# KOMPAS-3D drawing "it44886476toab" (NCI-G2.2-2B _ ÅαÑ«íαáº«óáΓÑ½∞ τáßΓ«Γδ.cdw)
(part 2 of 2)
  Кривая без истории:10764
  Кривая без истории:10765
  Кривая без истории:10766
  Кривая без истории:10767
  Кривая без истории:10768
  Кривая без истории:10769
  Кривая без истории:10770
  Кривая без истории:10771
  Кривая без истории:10772
  Кривая без истории:10773
  Кривая без истории:10774
  Кривая без истории:10775
  Кривая без истории:10776
  Кривая без истории:10777
  Кривая без истории:10778
  Кривая без истории:10779
  Кривая без истории:10780
  Кривая без истории:10781
  Кривая без истории:10782
  Кривая без истории:10783
  Кривая без истории:10784
  Кривая без истории:10785
  Кривая без истории:10786
  Кривая без истории:10787
  Кривая без истории:10788
  Кривая без истории:10789
  Кривая без истории:10790
  Кривая без истории:10791
  Кривая без истории:10792
  Кривая без истории:10793
  Кривая без истории:10794
  Кривая без истории:10795
  Кривая без истории:10796
  Кривая без истории:10797
  Кривая без истории:10798
  Кривая без истории:10799
  Кривая без истории:10800
  Кривая без истории:10801
  Кривая без истории:10802
  Кривая без истории:10803
  Кривая без истории:10804
  Кривая без истории:10805
  Кривая без истории:10806
  Кривая без истории:10807
  Кривая без истории:10808
  Кривая без истории:10809
  Кривая без истории:10810
  Кривая без истории:10811
  Кривая без истории:10812
  Кривая без истории:10813
  Кривая без истории:10814
  Кривая без истории:10815
  Кривая без истории:10816
  Кривая без истории:10817
  Кривая без истории:10818
  Кривая без истории:10819
  Кривая без истории:10820
  Кривая без истории:10821
  Кривая без истории:10822
  Кривая без истории:10823
  Кривая без истории:10824
  Кривая без истории:10825
  Кривая без истории:10826
  Кривая без истории:10827
  Кривая без истории:10828
  Кривая без истории:10829
  Кривая без истории:10830
  Кривая без истории:10831
  Кривая без истории:10832
  Кривая без истории:10833
  Кривая без истории:10834
  Кривая без истории:10835
  Кривая без истории:10836
  Кривая без истории:10837
  Кривая без истории:10838
  Кривая без истории:10839
  Кривая без истории:10840
  Кривая без истории:10841
  Кривая без истории:10842
  Кривая без истории:10843
  Кривая без истории:10844
  Кривая без истории:10845
  Кривая без истории:10846
  Кривая без истории:10847
  Кривая без истории:10848
  Кривая без истории:10849
  Кривая без истории:10850
  Кривая без истории:10851
  Кривая без истории:10852
  Кривая без истории:10853
  Кривая без истории:10854
  Кривая без истории:10855
  Кривая без истории:10856
  Кривая без истории:10857
  Кривая без истории:10858
  Кривая без истории:10859
  Кривая без истории:10860
  Кривая без истории:10861
  Кривая без истории:10862
  Кривая без истории:10863
  Кривая без истории:10864
  Кривая без истории:10865
  Кривая без истории:10866
  Кривая без истории:10867
  Кривая без истории:10868
  Кривая без истории:10869
  Кривая без истории:10870
  Кривая без истории:10871
  Кривая без истории:10872
  Кривая без истории:10873
  Кривая без истории:10874
  Кривая без истории:10875
  Кривая без истории:10876
  Кривая без истории:10877
  Кривая без истории:10878
  Кривая без истории:10879
  Кривая без истории:10880
  Кривая без истории:10881
  Кривая без истории:10882
  Кривая без истории:10883
  Кривая без истории:10884
  Кривая без истории:10885
  Кривая без истории:10886
  Кривая без истории:10887
  Кривая без истории:10888
  Кривая без истории:10889
  Кривая без истории:10890
  Кривая без истории:10891
  Кривая без истории:10892
  Кривая без истории:10893
  Кривая без истории:10894
  Кривая без истории:10895
  Кривая без истории:10896
  Кривая без истории:10897
  Кривая без истории:10898
  Кривая без истории:10899
  Кривая без истории:10900
  Кривая без истории:10901
  Кривая без истории:10902
  Кривая без истории:10903
  Кривая без истории:10904
  Кривая без истории:10905
  Кривая без истории:10906
  Кривая без истории:10907
  Кривая без истории:10908
  Кривая без истории:10909
  Кривая без истории:10910
  Кривая без истории:10911
  Кривая без истории:10912
  Кривая без истории:10913
  Кривая без истории:10914
  Кривая без истории:10915
  Кривая без истории:10916
  Кривая без истории:10917
  Кривая без истории:10918
  Кривая без истории:10919
  Кривая без истории:10920
  Кривая без истории:10921
  Кривая без истории:10922
  Кривая без истории:10923
  Кривая без истории:10924
  Кривая без истории:10925
  Кривая без истории:10926
  Кривая без истории:10927
  Кривая без истории:10928
  Кривая без истории:10929
  Кривая без истории:10930
  Кривая без истории:10931
  Кривая без истории:10932
  Кривая без истории:10933
  Кривая без истории:10934
  Кривая без истории:10935
  Кривая без истории:10936
  Кривая без истории:10937
  Кривая без истории:10938
  Кривая без истории:10939
  Кривая без истории:10940
  Кривая без истории:10941
  Кривая без истории:10942
  Кривая без истории:10943
  Кривая без истории:10944
  Кривая без истории:10945
  Кривая без истории:10946
  Кривая без истории:10947
  Кривая без истории:10948
  Кривая без истории:10949
  Кривая без истории:10950
  Кривая без истории:10951
  Кривая без истории:10952
  Кривая без истории:10953
  Кривая без истории:10954
  Кривая без истории:10955
  Кривая без истории:10956
  Кривая без истории:10957
  Кривая без истории:10958
  Кривая без истории:10959
  Кривая без истории:10960
  Кривая без истории:10961
  Кривая без истории:10962
  Кривая без истории:10963
  Кривая без истории:10964
  Кривая без истории:10965
  Кривая без истории:10966
  Кривая без истории:10967
  Кривая без истории:10968
  Кривая без истории:10969
  Кривая без истории:10970
  Кривая без истории:10971
  Кривая без истории:10972
  Кривая без истории:10973
  Кривая без истории:10974
  Кривая без истории:10975
  Кривая без истории:10976
  Кривая без истории:10977
  Кривая без истории:10978
  Кривая без истории:10979
  Кривая без истории:10980
  Кривая без истории:10981
  Кривая без истории:10982
  Кривая без истории:10983
  Кривая без истории:10984
  Кривая без истории:10985
  Кривая без истории:10986
  Кривая без истории:10987
  Кривая без истории:10988
  Кривая без истории:10989
  Кривая без истории:10990
  Кривая без истории:10991
  Кривая без истории:10992
  Кривая без истории:10993
  Кривая без истории:10994
  Кривая без истории:10995
  Кривая без истории:10996
  Кривая без истории:10997
  Кривая без истории:10998
  Кривая без истории:10999
  Кривая без истории:11000
  Кривая без истории:11001
  Кривая без истории:11002
  Кривая без истории:11003
  Кривая без истории:11004
  Кривая без истории:11005
  Кривая без истории:11006
  Кривая без истории:11007
  Кривая без истории:11008
  Кривая без истории:11009
  Кривая без истории:11010
  Кривая без истории:11011
  Кривая без истории:11012
  Кривая без истории:11013
  Кривая без истории:11014
  Кривая без истории:11015
  Кривая без истории:11016
  Кривая без истории:11017
  Кривая без истории:11018
  Кривая без истории:11019
  Кривая без истории:11020
  Кривая без истории:11021
  Кривая без истории:11022
  Кривая без истории:11023
  Кривая без истории:11024
  Кривая без истории:11025
  Кривая без истории:11026
  Кривая без истории:11027
  Кривая без истории:11028
  Кривая без истории:11029
  Кривая без истории:11030
  Кривая без истории:11031
  Кривая без истории:11032
  Кривая без истории:11033
  Кривая без истории:11034
  Кривая без истории:11035
  Кривая без истории:11036
  Кривая без истории:11037
  Кривая без истории:11038
  Кривая без истории:11039
  Кривая без истории:11040
  Кривая без истории:11041
  Кривая без истории:11042
  Кривая без истории:11043
  Кривая без истории:11044
  Кривая без истории:11045
  Кривая без истории:11046
  Кривая без истории:11047
  Кривая без истории:11048
  Кривая без истории:11049
  Кривая без истории:11050
  Кривая без истории:11051
  Кривая без истории:11052
  Кривая без истории:11053
  Кривая без истории:11054
  Кривая без истории:11055
  Кривая без истории:11056
  Кривая без истории:11057
  Кривая без истории:11058
  Кривая без истории:11059
  Кривая без истории:11060
  Кривая без истории:11061
  Кривая без истории:11062
  Кривая без истории:11063
  Кривая без истории:11064
  Кривая без истории:11065
  Кривая без истории:11066
  Кривая без истории:11067
  Кривая без истории:11068
  Кривая без истории:11069
  Кривая без истории:11070
  Кривая без истории:11071
  Кривая без истории:11072
  Кривая без истории:11073
  Кривая без истории:11074
  Кривая без истории:11075
  Кривая без истории:11076
  Кривая без истории:11077
  Кривая без истории:11078
  Кривая без истории:11079
  Кривая без истории:11080
  Кривая без истории:11081
  Кривая без истории:11082
  Кривая без истории:11083
  Кривая без истории:11084
  Кривая без истории:11085
  Кривая без истории:11086
  Кривая без истории:11087
  Кривая без истории:11088
  Кривая без истории:11089
  Кривая без истории:11090
  Кривая без истории:11091
  Кривая без истории:11092
  Кривая без истории:11093
  Кривая без истории:11094
  Кривая без истории:11095
  Кривая без истории:11096
  Кривая без истории:11097
  Кривая без истории:11098
  Кривая без истории:11099
  Кривая без истории:11100
  Кривая без истории:11101
  Кривая без истории:11102
  Кривая без истории:11103
  Кривая без истории:11104
  Кривая без истории:11105
  Кривая без истории:11106
  Кривая без истории:11107
  Кривая без истории:11108
  Кривая без истории:11109
  Кривая без истории:11110
  Кривая без истории:11111
  Кривая без истории:11112
  Кривая без истории:11113
  Кривая без истории:11114
  Кривая без истории:11115
  Кривая без истории:11116
  Кривая без истории:11117
  Кривая без истории:11118
  Кривая без истории:11119
  Кривая без истории:11120
  Кривая без истории:11121
  Кривая без истории:11122
  Кривая без истории:11123
  Кривая без истории:11124
  Кривая без истории:11125
  Кривая без истории:11126
  Кривая без истории:11127
  Кривая без истории:11128
  Кривая без истории:11129
  Кривая без истории:11130
  Кривая без истории:11131
  Кривая без истории:11132
  Кривая без истории:11133
  Кривая без истории:11134
  Кривая без истории:11135
  Кривая без истории:11136
  Кривая без истории:11137
  Кривая без истории:11138
  Кривая без истории:11139
  Кривая без истории:11140
  Кривая без истории:11141
  Кривая без истории:11142
  Кривая без истории:11143
  Кривая без истории:11144
  Кривая без истории:11145
  Кривая без истории:11146
  Кривая без истории:11147
  Кривая без истории:11148
  Кривая без истории:11149
  Кривая без истории:11150
  Кривая без истории:11151
  Кривая без истории:11152
  Кривая без истории:11153
  Кривая без истории:11154
  Кривая без истории:11155
  Кривая без истории:11156
  Кривая без истории:11157
  Кривая без истории:11158
  Кривая без истории:11159
  Кривая без истории:11160
  Кривая без истории:11161
  Кривая без истории:11162
  Кривая без истории:11163
  Кривая без истории:11164
  Кривая без истории:11165
  Кривая без истории:11166
  Кривая без истории:11167
  Кривая без истории:11168
  Кривая без истории:11169
  Кривая без истории:11170
  Кривая без истории:11171
  Кривая без истории:11172
  Кривая без истории:11173
  Кривая без истории:11174
  Кривая без истории:11175
  Кривая без истории:11176
  Кривая без истории:11177
  Кривая без истории:11178
  Кривая без истории:11179
  Кривая без истории:11180
  Кривая без истории:11181
  Кривая без истории:11182
  Кривая без истории:11183
  Кривая без истории:11184
  Кривая без истории:11185
  Кривая без истории:11186
  Кривая без истории:11187
  Кривая без истории:11188
  Кривая без истории:11189
  Кривая без истории:11190
  Кривая без истории:11191
  Кривая без истории:11192
  Кривая без истории:11193
  Кривая без истории:11194
  Кривая без истории:11195
  Кривая без истории:11196
  Кривая без истории:11197
  Кривая без истории:11198
  Кривая без истории:11199
  Кривая без истории:11200
  Кривая без истории:11201
  Кривая без истории:11202
  Кривая без истории:11203
  Кривая без истории:11204
  Кривая без истории:11205
  Кривая без истории:11206
  Кривая без истории:11207
  Кривая без истории:11208
  Кривая без истории:11209
  Кривая без истории:11210
  Кривая без истории:11211
  Кривая без истории:11212
  Кривая без истории:11213
  Кривая без истории:11214
  Кривая без истории:11215
  Кривая без истории:11216
  Кривая без истории:11217
  Кривая без истории:11218
  Кривая без истории:11219
  Кривая без истории:11220
  Кривая без истории:11221
  Кривая без истории:11222
  Кривая без истории:11223
  Кривая без истории:11224
  Кривая без истории:11225
  Кривая без истории:11226
  Кривая без истории:11227
  Кривая без истории:11228
  Кривая без истории:11229
  Кривая без истории:11230
  Кривая без истории:11231
  Кривая без истории:11232
  Кривая без истории:11233
  Кривая без истории:11234
  Кривая без истории:11235
  Кривая без истории:11236
  Кривая без истории:11237
  Кривая без истории:11238
  Кривая без истории:11239
  Кривая без истории:11240
  Кривая без истории:11241
  Кривая без истории:11242
  Кривая без истории:11243
  Кривая без истории:11244
  Кривая без истории:11245
  Кривая без истории:11246
  Кривая без истории:11247
  Кривая без истории:11248
  Кривая без истории:11249
  Кривая без истории:11250
  Кривая без истории:11251
  Кривая без истории:11252
  Кривая без истории:11253
  Кривая без истории:11254
  Кривая без истории:11255
  Кривая без истории:11256
  Кривая без истории:11257
  Кривая без истории:11258
  Кривая без истории:11259
  Кривая без истории:11260
  Кривая без истории:11261
  Кривая без истории:11262
  Кривая без истории:11263
  Кривая без истории:11264
  Кривая без истории:11265
  Кривая без истории:11266
  Кривая без истории:11267
  Кривая без истории:11268
  Кривая без истории:11269
  Кривая без истории:11270
  Кривая без истории:11271
  Кривая без истории:11272
  Кривая без истории:11273
  Кривая без истории:11274
  Кривая без истории:11275
  Кривая без истории:11276
  Кривая без истории:11277
  Кривая без истории:11278
  Кривая без истории:11279
  Кривая без истории:11280
  Кривая без истории:11281
  Кривая без истории:11282
  Кривая без истории:11283
  Кривая без истории:11284
  Кривая без истории:11285
  Кривая без истории:11286
  Кривая без истории:11287
  Кривая без истории:11288
  Кривая без истории:11289
  Кривая без истории:11290
  Кривая без истории:11291
  Кривая без истории:11292
  Кривая без истории:11293
  Кривая без истории:11294
  Кривая без истории:11295
  Кривая без истории:11296
  Кривая без истории:11297
  Кривая без истории:11298
  Кривая без истории:11299
  Кривая без истории:11300
  Кривая без истории:11301
  Кривая без истории:11302
  Кривая без истории:11303
  Кривая без истории:11304
  Кривая без истории:11305
  Кривая без истории:11306
  Кривая без истории:11307
  Кривая без истории:11308
  Кривая без истории:11309
  Кривая без истории:11310
  Кривая без истории:11311
  Кривая без истории:11312
  Кривая без истории:11313
  Кривая без истории:11314
  Кривая без истории:11315
  Кривая без истории:11316
  Кривая без истории:11317
  Кривая без истории:11318
  Кривая без истории:11319
  Кривая без истории:11320
  Кривая без истории:11321
  Кривая без истории:11322
  Кривая без истории:11323
  Кривая без истории:11324
  Кривая без истории:11325
  Кривая без истории:11326
  Кривая без истории:11327
  Кривая без истории:11328
  Кривая без истории:11329
  Кривая без истории:11330
  Кривая без истории:11331
  Кривая без истории:11332
  Кривая без истории:11333
  Кривая без истории:11334
  Кривая без истории:11335
  Кривая без истории:11336
  Кривая без истории:11337
  Кривая без истории:11338
  Кривая без истории:11339
  Кривая без истории:11340
  Кривая без истории:11341
  Кривая без истории:11342
  Кривая без истории:11343
  Кривая без истории:11344
  Кривая без истории:11345
  Кривая без истории:11346
  Кривая без истории:11347
  Кривая без истории:11348
  Кривая без истории:11349
  Кривая без истории:11350
  Кривая без истории:11351
  Кривая без истории:11352
  Кривая без истории:11353
  Кривая без истории:11354
  Кривая без истории:11355
  Кривая без истории:11356
  Кривая без истории:11357
  Кривая без истории:11358
  Кривая без истории:11359
  Кривая без истории:11360
  Кривая без истории:11361
  Кривая без истории:11362
  Кривая без истории:11363
  Кривая без истории:11364
  Кривая без истории:11365
  Кривая без истории:11366
  Кривая без истории:11367
  Кривая без истории:11368
  Кривая без истории:11369
  Кривая без истории:11370
  Кривая без истории:11371
  Кривая без истории:11372
  Кривая без истории:11373
  Кривая без истории:11374
  Кривая без истории:11375
  Кривая без истории:11376
  Кривая без истории:11377
  Кривая без истории:11378
  Кривая без истории:11379
  Кривая без истории:11380
  Кривая без истории:11381
  Кривая без истории:11382
  Кривая без истории:11383
  Кривая без истории:11384
  Кривая без истории:11385
  Кривая без истории:11386
  Кривая без истории:11387
  Кривая без истории:11388
  Кривая без истории:11389
  Кривая без истории:11390
  Кривая без истории:11391
  Кривая без истории:11392
  Кривая без истории:11393
  Кривая без истории:11394
  Кривая без истории:11395
  Кривая без истории:11396
  Кривая без истории:11397
  Кривая без истории:11398
  Кривая без истории:11399
  Кривая без истории:11400
  Кривая без истории:11401
  Кривая без истории:11402
  Кривая без истории:11403
  Кривая без истории:11404
  Кривая без истории:11405
  Кривая без истории:11406
  Кривая без истории:11407
  Кривая без истории:11408
  Кривая без истории:11409
  Кривая без истории:11410
  Кривая без истории:11411
  Кривая без истории:11412
  Кривая без истории:11413
  Кривая без истории:11414
  Кривая без истории:11415
  Кривая без истории:11416
  Кривая без истории:11417
  Кривая без истории:11418
  Кривая без истории:11419
  Кривая без истории:11420
  Кривая без истории:11421
  Кривая без истории:11422
  Кривая без истории:11423
  Кривая без истории:11424
  Кривая без истории:11425
  Кривая без истории:11426
  Кривая без истории:11427
  Кривая без истории:11428
  Кривая без истории:11429
  Кривая без истории:11430
  Кривая без истории:11431
  Кривая без истории:11432
  Кривая без истории:11433
  Кривая без истории:11434
  Кривая без истории:11435
  Кривая без истории:11436
  Кривая без истории:11437
  Кривая без истории:11438
  Кривая без истории:11439
  Кривая без истории:11440
  Кривая без истории:11441
  Кривая без истории:11442
  Кривая без истории:11443
  Кривая без истории:11444
  Кривая без истории:11445
  Кривая без истории:11446
  Кривая без истории:11447
  Кривая без истории:11448
  Кривая без истории:11449
  Кривая без истории:11450
  Кривая без истории:11451
  Кривая без истории:11452
  Кривая без истории:11453
  Кривая без истории:11454
  Кривая без истории:11455
  Кривая без истории:11456
  Кривая без истории:11457
  Кривая без истории:11458
  Кривая без истории:11459
  Кривая без истории:11460
  Кривая без истории:11461
  Кривая без истории:11462
  Кривая без истории:11463
  Кривая без истории:11464
  Кривая без истории:11465
  Кривая без истории:11466
  Кривая без истории:11467
  Кривая без истории:11468
  Кривая без истории:11469
  Кривая без истории:11470
  Кривая без истории:11471
  Кривая без истории:11472
  Кривая без истории:11473
  Кривая без истории:11474
  Кривая без истории:11475
  Кривая без истории:11476
  Кривая без истории:11477
  Кривая без истории:11478
  Кривая без истории:11479
  Кривая без истории:11480
  Кривая без истории:11481
  Кривая без истории:11482
  Кривая без истории:11483
  Кривая без истории:11484
  Кривая без истории:11485
  Кривая без истории:11486
  Кривая без истории:11487
  Кривая без истории:11488
  Кривая без истории:11489
  Кривая без истории:11490
  Кривая без истории:11491
  Кривая без истории:11492
  Кривая без истории:11493
  Кривая без истории:11494
  Кривая без истории:11495
  Кривая без истории:11496
  Кривая без истории:11497
  Кривая без истории:11498
  Кривая без истории:11499
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Dimensions and other numbers on the sheet: 4±1; 1:1; 1; 13.01.25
